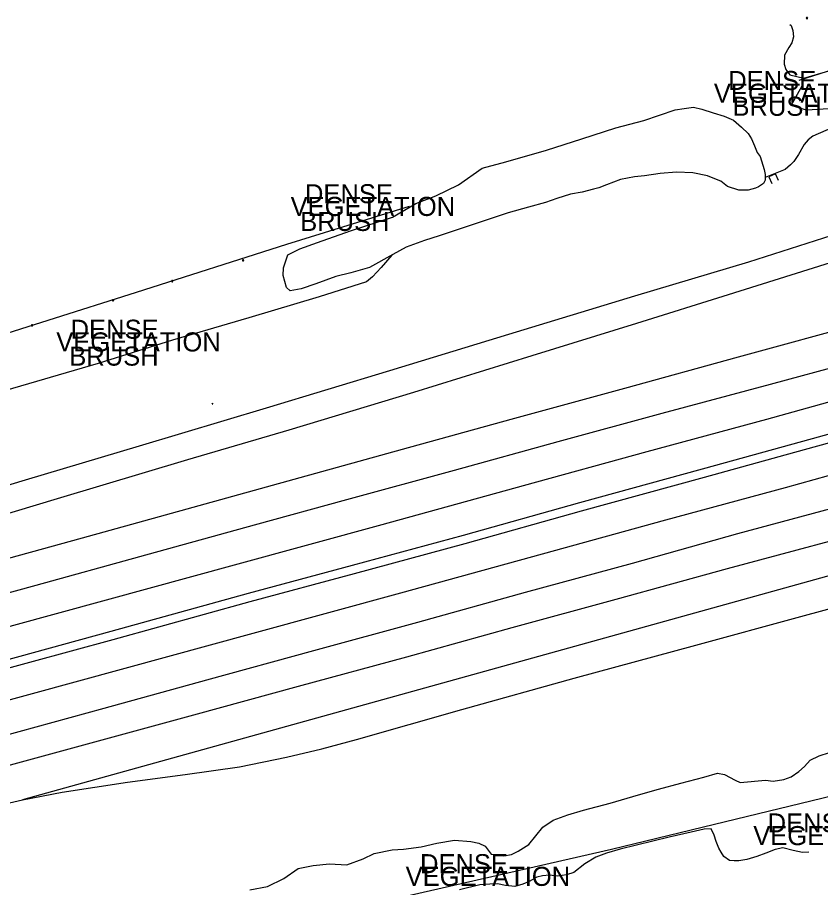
# Model space of a CAD drawing. Extents: x 2129547 to 2134906, y 657330 to 659734.
# Drawn here: x 2130531.7 to 2130826.3, y 657907.3 to 658226.6 of the extents above; entities that cross this region are included whole.
import ezdxf

# ---------------------------------------------------------------- set-up
doc = ezdxf.new("R2010")
doc.units = 0
for name, color, linetype in [('Default', 7, 'Continuous'), ('DR_X_Culvert', 7, 'Continuous'), ('LT_X_Poles', 7, 'Continuous'), ('PM_X_Edge_Line', 7, 'Continuous'), ('PM_X_Lane_Line', 7, 'Continuous'), ('PM_X_LaneDOT', 7, 'Continuous'), ('PV_X_EOP2', 7, 'Continuous'), ('PV_X_Shoulder', 7, 'Continuous'), ('RD_X_Concrete_Barrier', 7, 'Continuous'), ('RD_X_Fence', 7, 'Continuous'), ('VG_X_Cells', 7, 'Continuous'), ('VG_X_Shrub_Line_Lt', 7, 'Continuous'), ('VG_X_Text', 7, 'Continuous'), ('VG_X_Tree_Line_Lt', 7, 'Continuous')]:
    doc.layers.add(name, color=color, linetype=linetype)

# ---------------------------------------------------------------- blocks, each defined once
blk = doc.blocks.new('PIPE')
at = {"layer": 'Default'}
for p, q in [((0.135, 0.067), (0, 0.067)), ((0, 0.067), (0, -0.067)), ((0, -0.067), (0.135, -0.067))]:
    blk.add_line(p, q, dxfattribs=at)

msp = doc.modelspace()

# ---------------------------------------------------------------- linework, layer by layer
at = {"layer": 'LT_X_Poles'}
msp.add_lwpolyline([(2130603.2, 658085.01), (2130603.12, 658084.71), (2130603.24, 658084.71)], dxfattribs=at)
msp.add_circle((2130603.16, 658084.86), 0.065, dxfattribs=at)
at = {"layer": 'PM_X_Edge_Line'}
for points in [[(2130507.73, 658038.43), (2130546.43, 658050.14), (2130594.19, 658064.34), (2130631.31, 658075.34), (2130677.05, 658089.14), (2130720.52, 658102.5), (2130758.97, 658114.48), (2130792.54, 658124.9), (2130834.3, 658137.98), (2130861.02, 658146.3), (2130876.51, 658151.19)], [(2129783, 657797.65), (2129820.8, 657807.78), (2129922.27, 657836.17), (2129994.45, 657856.25), (2130028.21, 657865.49), (2130093.84, 657883.42), (2130153.98, 657899.99), (2130199.12, 657912.39), (2130249.09, 657926.31), (2130302.49, 657941.01), (2130341.07, 657951.58), (2130345.17, 657952.7), (2130404.65, 657969.17), (2130458.77, 657984.04), (2130511.95, 657998.61), (2130564.35, 658012.89), (2130611.28, 658025.79), (2130665.46, 658040.53), (2130717.36, 658054.84), (2130762.68, 658067.32), (2130806.63, 658079.2), (2130851.4, 658091.68), (2130882.88, 658100.31), (2130891, 658102.57)], [(2129782.31, 657770.56), (2129838.02, 657785.8), (2129918.94, 657807.73), (2130006.57, 657832.43), (2130060.5, 657847.21), (2130112.38, 657861.87), (2130166.66, 657876.43), (2130223.01, 657891.92), (2130282.32, 657908.07), (2130309.12, 657915.87), (2130347.7, 657926.43), (2130352.07, 657927.63), (2130411.57, 657944.11), (2130465.65, 657958.97), (2130518.8, 657973.53), (2130571.22, 657987.81), (2130618.14, 658000.71), (2130672.33, 658015.45), (2130724.27, 658029.78), (2130769.53, 658042.24), (2130813.51, 658054.13), (2130850.23, 658064.39), (2130880.11, 658072.6), (2130898.43, 658077.6)], [(2130514.96, 657935.23), (2130533.56, 657939.51), (2130548.13, 657942.33), (2130572.12, 657946.01), (2130593.17, 657948.82), (2130613.14, 657951.57), (2130630.34, 657955.2), (2130643.38, 657958.22), (2130656.02, 657961.69), (2130694.77, 657972.7), (2130735.95, 657984.14), (2130780.51, 657996.29), (2130819.12, 658006.73), (2130865.97, 658019.55), (2130885.83, 658025.06), (2130910.2, 658031.7), (2130911.96, 658032.18)]]:
    msp.add_lwpolyline(points, dxfattribs=at)
at = {"layer": 'PM_X_Lane_Line'}
for points in [[(2130517.26, 658025.11), (2130555.6, 658035.62), (2130596.09, 658046.96), (2130635.43, 658057.75), (2130673, 658068.21), (2130712.86, 658079.14), (2130754.47, 658090.52), (2130796.26, 658102.11), (2130842.82, 658114.83), (2130877.34, 658124.38), (2130883.95, 658126.23)], [(2130499.23, 658007.56), (2130538.61, 658018.28), (2130576.6, 658028.77), (2130618.67, 658040.36), (2130652.58, 658049.68), (2130692.07, 658060.48), (2130730.09, 658071.06), (2130768.24, 658081.36), (2130807.99, 658092.09), (2130836.01, 658099.68), (2130859, 658106.14), (2130884.83, 658113.47), (2130887.53, 658114.21)], [(2130526.03, 657962.85), (2130563.47, 657973.17), (2130601.11, 657983.57), (2130640.45, 657994.25), (2130678.58, 658004.73), (2130718.03, 658015.65), (2130757.3, 658026.31), (2130795.99, 658037.18), (2130835.05, 658047.79), (2130858.29, 658053.7), (2130885.63, 658061.39), (2130901.91, 658065.91)], [(2130905.13, 658055.12), (2130882.94, 658049.03), (2130855.07, 658041.17), (2130792.06, 658024.31), (2130751.21, 658013.06), (2130713.04, 658002.57), (2130674.42, 657991.9), (2130634.64, 657981.1), (2130596.28, 657970.59), (2130557.28, 657959.92), (2130518.18, 657949.28)]]:
    msp.add_lwpolyline(points, dxfattribs=at)
at = {"layer": 'PM_X_LaneDOT'}
msp.add_lwpolyline([(2130908.51, 658043.78), (2130890.08, 658038.64), (2130533.56, 657939.51)], dxfattribs=at)
at = {"layer": 'PV_X_EOP2'}
for points in [[(2130507.73, 658038.43), (2130546.43, 658050.14), (2130594.19, 658064.34), (2130631.31, 658075.34), (2130677.05, 658089.14), (2130720.52, 658102.5), (2130758.97, 658114.48), (2130792.54, 658124.9), (2130834.3, 658137.98), (2130861.02, 658146.3), (2130876.51, 658151.19)], [(2129783, 657797.65), (2129820.8, 657807.78), (2129922.27, 657836.17), (2129994.45, 657856.25), (2130028.21, 657865.49), (2130093.84, 657883.42), (2130153.98, 657899.99), (2130199.12, 657912.39), (2130249.09, 657926.31), (2130302.49, 657941.01), (2130341.07, 657951.58), (2130345.17, 657952.7), (2130404.65, 657969.17), (2130458.77, 657984.04), (2130511.95, 657998.61), (2130564.35, 658012.89), (2130611.28, 658025.79), (2130665.46, 658040.53), (2130717.36, 658054.84), (2130762.68, 658067.32), (2130806.63, 658079.2), (2130851.4, 658091.68), (2130882.88, 658100.31), (2130891, 658102.57)], [(2129782.31, 657770.56), (2129838.02, 657785.8), (2129918.94, 657807.73), (2130006.57, 657832.43), (2130060.5, 657847.21), (2130112.38, 657861.87), (2130166.66, 657876.43), (2130223.01, 657891.92), (2130282.32, 657908.07), (2130309.12, 657915.87), (2130347.7, 657926.43), (2130352.07, 657927.63), (2130411.57, 657944.11), (2130465.65, 657958.97), (2130518.8, 657973.53), (2130571.22, 657987.81), (2130618.14, 658000.71), (2130672.33, 658015.45), (2130724.27, 658029.78), (2130769.53, 658042.24), (2130813.51, 658054.13), (2130850.23, 658064.39), (2130880.11, 658072.6), (2130898.43, 658077.6)], [(2130514.96, 657935.23), (2130533.56, 657939.51), (2130548.13, 657942.33), (2130572.12, 657946.01), (2130593.17, 657948.82), (2130613.14, 657951.57), (2130630.34, 657955.2), (2130643.38, 657958.22), (2130656.02, 657961.69), (2130694.77, 657972.7), (2130735.95, 657984.14), (2130780.51, 657996.29), (2130819.12, 658006.73), (2130865.97, 658019.55), (2130885.83, 658025.06), (2130910.2, 658031.7), (2130911.96, 658032.18)]]:
    msp.add_lwpolyline(points, dxfattribs=at)
at = {"layer": 'PV_X_Shoulder'}
msp.add_lwpolyline([(2130494.01, 658044.69), (2130534.58, 658056.98), (2130576.5, 658069.39), (2130623.09, 658083.36), (2130668.35, 658097.03), (2130711.95, 658110.36), (2130758.22, 658124.46), (2130800.02, 658136.99), (2130830.63, 658146.71), (2130850.86, 658153), (2130868.47, 658158.15), (2130873.95, 658159.78)], dxfattribs=at)
at = {"layer": 'RD_X_Concrete_Barrier'}
for points in [[(2130894.27, 658091.58), (2130878, 658087.11), (2130853.36, 658080.31), (2130816.1, 658070.01), (2130782.91, 658060.82), (2130737.86, 658048.46), (2130695.16, 658036.46), (2130654.54, 658025.52), (2130616.29, 658015.21), (2130565.99, 658001.27), (2130519.98, 657988.71)], [(2130520.77, 657985.82), (2130566.78, 657998.38), (2130617.08, 658012.31), (2130655.32, 658022.62), (2130695.96, 658033.57), (2130738.66, 658045.57), (2130783.7, 658057.93), (2130816.89, 658067.12), (2130854.16, 658077.41), (2130878.8, 658084.22), (2130895.13, 658088.7)]]:
    msp.add_lwpolyline(points, dxfattribs=at)
at = {"layer": 'RD_X_Fence'}
msp.add_line((2130838.77, 658210.01), (2130818.36, 658203.49), dxfattribs=at)
for points in [[(2130675.45, 658157.25), (2130630.36, 658143.32), (2130575.2, 658125.7), (2130510.26, 658105.12), (2130445.93, 658085.48), (2130377.98, 658066.47), (2130315.31, 658049.26)], [(2130372.76, 657831.4), (2130401.89, 657841.24), (2130444.91, 657852.66), (2130493.65, 657863.34), (2130547.6, 657875.39), (2130589.68, 657885.4), (2130636.62, 657895.64), (2130749.57, 657921.43), (2130795.47, 657932.48), (2130846.52, 657944.86), (2130897.31, 657956.97), (2130898.55, 657989.46), (2130902.91, 657992.37), (2130925.34, 657969.73), (2130931.96, 657970.88)]]:
    msp.add_lwpolyline(points, dxfattribs=at)
at = {"layer": 'VG_X_Cells'}
for centre in [(2130821.33, 658226.39), (2130614.45, 658137.48), (2130588.45, 658129.83), (2130566.79, 658122.77), (2130537.07, 658113.63)]:
    msp.add_circle(centre, 0.012, dxfattribs=at)
for centre, radius, start, end in [((2130821.16, 658226.49), 0.0735, 39.0625, 279.5412), ((2130821.19, 658226.31), 0.0987, 96.1722, 320.5737), ((2130821.28, 658226.56), 0.0658, 354.0047, 205.9741), ((2130821.38, 658226.26), 0.114, 184.9476, 19.4572), ((2130821.42, 658226.53), 0.0776, 323.83, 165.0376), ((2130821.5, 658226.39), 0.0957, 259.1453, 101.4596), ((2130614.28, 658137.57), 0.0735, 39.0625, 279.5412), ((2130614.31, 658137.4), 0.0987, 96.1722, 320.5737), ((2130614.4, 658137.65), 0.0658, 354.0047, 205.9741), ((2130614.5, 658137.35), 0.114, 184.9476, 19.4572), ((2130614.54, 658137.62), 0.0776, 323.83, 165.0376), ((2130614.62, 658137.48), 0.0957, 259.1453, 101.4596), ((2130588.31, 658129.75), 0.0987, 96.1722, 320.5737), ((2130588.29, 658129.92), 0.0735, 39.0625, 279.5412), ((2130588.41, 658130), 0.0658, 354.0047, 205.9741), ((2130588.5, 658129.7), 0.114, 184.9476, 19.4572), ((2130588.55, 658129.97), 0.0776, 323.83, 165.0376), ((2130588.63, 658129.83), 0.0957, 259.1453, 101.4596), ((2130566.64, 658122.7), 0.0987, 96.1722, 320.5737), ((2130566.62, 658122.87), 0.0735, 39.0625, 279.5412), ((2130566.74, 658122.94), 0.0658, 354.0047, 205.9741), ((2130566.83, 658122.64), 0.114, 184.9476, 19.4572), ((2130566.88, 658122.91), 0.0776, 323.83, 165.0376), ((2130566.96, 658122.78), 0.0957, 259.1453, 101.4596), ((2130536.9, 658113.72), 0.0735, 39.0625, 279.5412), ((2130536.93, 658113.55), 0.0987, 96.1722, 320.5737), ((2130537.02, 658113.79), 0.0658, 354.0047, 205.9741), ((2130537.12, 658113.5), 0.114, 184.9476, 19.4572), ((2130537.16, 658113.77), 0.0776, 323.83, 165.0376), ((2130537.24, 658113.63), 0.0957, 259.1453, 101.4596)]:
    msp.add_arc(centre, radius, start, end, dxfattribs=at)
at = {"layer": 'VG_X_Shrub_Line_Lt'}
for points in [[(2130815.05, 658223.98), (2130815.52, 658223.7), (2130816.19, 658221.85), (2130816.39, 658219.55), (2130815.82, 658217.24), (2130814.65, 658215.57), (2130813.03, 658212.76), (2130813, 658209.45), (2130813.61, 658207.5), (2130815.06, 658205.56), (2130820.22, 658204.37)], [(2130839.74, 658193.73), (2130837.13, 658190.62), (2130836, 658189.34), (2130833.61, 658187.34), (2130829.06, 658185.47), (2130825.43, 658183.94), (2130823.54, 658183.02), (2130821.8, 658181.74), (2130820.27, 658179.97), (2130818.27, 658176.29), (2130816.51, 658173.69), (2130815.34, 658172.48), (2130813.33, 658170.8), (2130805.95, 658167.89)], [(2130669.01, 658139.36), (2130665.12, 658134.81), (2130661.91, 658131.37), (2130659.7, 658129.53), (2130642.34, 658124.05), (2130616.59, 658116.37), (2130588.6, 658108.14), (2130561.25, 658099.58), (2130523.84, 658088.76)]]:
    msp.add_lwpolyline(points, dxfattribs=at)
at = {"layer": 'VG_X_Tree_Line_Lt'}
for points in [[(2130862.64, 658197.78), (2130857.69, 658196.33), (2130843.37, 658193.96), (2130821.2, 658192.57), (2130815.57, 658194.27), (2130819.56, 658201.51), (2130820.22, 658204.37), (2130848.17, 658212.54), (2130856.69, 658217.74)], [(2130772.99, 658192.71), (2130776.25, 658193.23), (2130779.66, 658193.64), (2130782.74, 658192.9), (2130786.91, 658191.6), (2130791.01, 658190.33), (2130794.4, 658188.97), (2130797.34, 658186.39), (2130799.78, 658184.01), (2130800.95, 658182.08), (2130802.11, 658179.45), (2130803.06, 658177.01), (2130804.21, 658175.58), (2130805.62, 658170.79), (2130805.94, 658168.93), (2130805.95, 658166.95), (2130805.42, 658165.65), (2130803.54, 658164.46), (2130802.46, 658163.95), (2130799.71, 658163.27), (2130796.35, 658163.28), (2130792.14, 658164.52), (2130789.7, 658166.53), (2130788.13, 658167.2), (2130784.82, 658168.43), (2130779.41, 658169.55), (2130773.44, 658169.86), (2130767.44, 658169.34), (2130761.7, 658168.5), (2130758.07, 658168.1), (2130752.88, 658167.09), (2130747.76, 658165.13), (2130744.96, 658164.14), (2130743.05, 658163.57), (2130738.83, 658162.55), (2130734.55, 658161.81), (2130729.62, 658160.19), (2130725.46, 658158.76), (2130719.12, 658157.01), (2130711.7, 658154.88), (2130706.98, 658153.37), (2130686.38, 658146.51), (2130681.02, 658144.7), (2130674.24, 658142.32), (2130669.42, 658139.59), (2130660.82, 658134.85), (2130653.95, 658132.89), (2130648.46, 658131.57), (2130641.11, 658128.81), (2130635.77, 658126.98), (2130631.74, 658126.28), (2130630.39, 658127.56), (2130629.21, 658131.91), (2130629.33, 658134.73), (2130630.87, 658139.56), (2130635.25, 658141.7), (2130641.81, 658144.03), (2130653.82, 658148.29), (2130669.32, 658153.32), (2130677.88, 658158.31), (2130685.23, 658161.15), (2130693.48, 658165.17), (2130702.15, 658171.29), (2130710.85, 658173.61), (2130725.72, 658177.87), (2130738.78, 658182.01), (2130751.17, 658186.13), (2130761.45, 658188.76), (2130772.99, 658192.71)], [(2130806.14, 657946.69), (2130808.98, 657946.4), (2130812.83, 657946.93), (2130815.49, 657947.98), (2130818.4, 657949.88), (2130820.48, 657951.74), (2130822.53, 657954.04), (2130825.76, 657955.71), (2130829.61, 657956.91)], [(2130616.99, 657906.51), (2130623.45, 657907.71), (2130629.42, 657910.68), (2130634.62, 657914.25), (2130640.17, 657915.46), (2130646.19, 657916.05), (2130652.56, 657915.71), (2130658.48, 657917.91), (2130662.51, 657919.8), (2130669.2, 657921.14), (2130673.32, 657921.41), (2130679.75, 657922.26), (2130685.55, 657923.6), (2130692.06, 657924.67), (2130697.98, 657924.18), (2130700.91, 657923.55), (2130703.22, 657922.48), (2130705.46, 657919.55), (2130710.08, 657918.95), (2130712.99, 657919.49), (2130715.4, 657920.68), (2130719.28, 657923.14), (2130724.39, 657929.48), (2130728.27, 657932.08), (2130733.61, 657934.05), (2130739.4, 657935.66), (2130749.08, 657938.31), (2130759.56, 657941.31), (2130766.85, 657943.45), (2130775.03, 657945.65), (2130783.48, 657947.88), (2130788.56, 657949.27), (2130791.07, 657948.85), (2130795.04, 657946.7), (2130796.77, 657945.91), (2130806.14, 657946.69)], [(2130821.96, 657920.25), (2130819.72, 657920.19), (2130816.21, 657920.94), (2130812.49, 657921.91), (2130809.65, 657921.32), (2130806.2, 657919.92), (2130802.91, 657918.72), (2130799.24, 657917.59), (2130796.36, 657917.18), (2130794.61, 657917.08), (2130792.86, 657917.27), (2130790.86, 657918.71), (2130789.81, 657920.27), (2130789.03, 657921.74), (2130788.07, 657924.16), (2130787.23, 657926.52), (2130786.16, 657928.86), (2130783.56, 657928.73), (2130778.79, 657927.62), (2130770.84, 657925.85), (2130752.83, 657921.38), (2130747.81, 657919.93), (2130743.83, 657918.52), (2130739.83, 657916), (2130735.77, 657912.78), (2130733.08, 657911.94), (2130729.9, 657911.47), (2130726.9, 657911.82), (2130724.31, 657911.63), (2130722.18, 657911.1), (2130719.4, 657909.57), (2130717.15, 657908.52), (2130714.21, 657907.69), (2130710.73, 657908.08), (2130707.77, 657908.65), (2130705, 657908.52), (2130701.32, 657908.32), (2130693.81, 657906.49)]]:
    msp.add_lwpolyline(points, dxfattribs=at)

# ---------------------------------------------------------------- block references
at = {"layer": 'DR_X_Culvert', "xscale": 19.685, "yscale": 19.685000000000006, "rotation": -65.99122877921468}
msp.add_blockref('PIPE', (2130808.56, 658168.64), dxfattribs=at)

# ---------------------------------------------------------------- texts
at = {"layer": 'VG_X_Text'}
for s, p in [('DENSE', (2130792.44, 658199.97)), ('VEGETATION', (2130787.19, 658195.31)), ('BRUSH', (2130794.01, 658190.52)), ('DENSE', (2130637.17, 658158.43)), ('VEGETATION', (2130631.91, 658153.77)), ('BRUSH', (2130635.43, 658148.26)), ('DENSE', (2130551.2, 658108.69)), ('VEGETATION', (2130545.94, 658104.04)), ('BRUSH', (2130550.71, 658098.84)), ('DENSE', (2130806.91, 657927.53)), ('VEGETATION', (2130801.65, 657922.88)), ('DENSE', (2130679.38, 657912.58)), ('VEGETATION', (2130674.12, 657907.92))]:
    msp.add_text(s, height=7, dxfattribs=at).set_placement(p)

doc.saveas('drawing.dxf')
